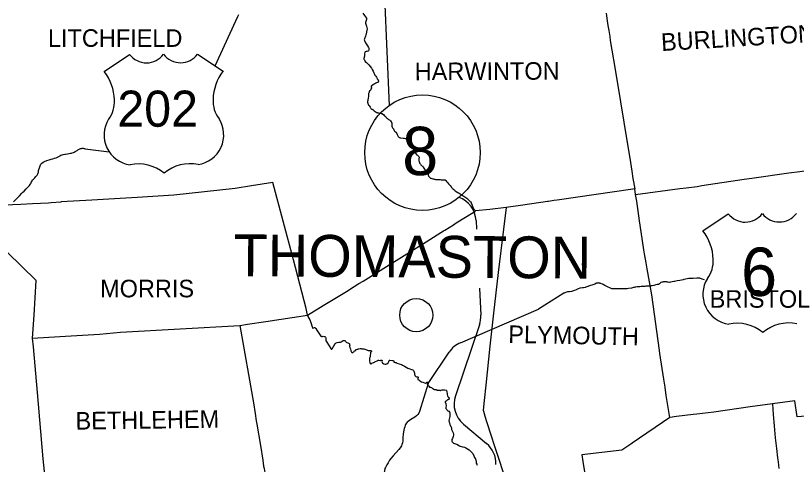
# Model space of a CAD drawing. Extents: x 0 to 2603, y -226 to 830.
# Drawn here: x 100.6 to 160.6, y 606.3 to 640.7 of the extents above; entities that cross this region are included whole.
import ezdxf

# ---------------------------------------------------------------- set-up
doc = ezdxf.new("R2010")
doc.units = 0
for name, color, linetype in [('CT_TSH_Map_Cities_Text', 7, 'Continuous'), ('CT_TSH_Map_Districts', 7, 'Continuous'), ('CT_TSH_Map_Town_Limits', 7, 'Continuous'), ('CT_TSH_Map_Town_Text', 7, 'Continuous'), ('CT_TSH_Map_US_and_State_Routes', 7, 'Continuous')]:
    doc.layers.add(name, color=color, linetype=linetype)

msp = doc.modelspace()

# ---------------------------------------------------------------- linework, layer by layer
at = {"layer": 'CT_TSH_Map_Cities_Text'}
msp.add_circle((131.429, 617.742), 1.277, dxfattribs=at)
at = {"layer": 'CT_TSH_Map_Districts'}
for points in [[(148.278, 627.02), (151.681, 627.475), (152.152, 627.53), (153.003, 627.633), (153.352, 627.689), (156.611, 628.19), (157.203, 628.271), (160.048, 628.681), (160.888, 628.784), (161.63, 628.881), (162.448, 629.002), (165.876, 629.461)], [(150.903, 609.889), (150.633, 611.58), (150.537, 612.202), (150.436, 612.824), (150.125, 614.791), (150.099, 615.029), (149.51, 619.3), (149.173, 621.288), (149.092, 621.768), (148.963, 622.452), (148.9, 622.761), (148.702, 624.138), (148.571, 624.979), (148.361, 626.488), (148.278, 627.02)], [(150.903, 609.889), (148.007, 607.903), (147.918, 607.835), (147.204, 607.367), (144.141, 607.01), (144.225, 606.511), (144.636, 603.968)]]:
    msp.add_lwpolyline(points, dxfattribs=at)
at = {"layer": 'CT_TSH_Map_Town_Limits'}
for points in [[(127.331, 640.938), (127.455, 640.745), (127.601, 640.541), (127.614, 640.495), (127.609, 640.455), (127.561, 640.307), (127.529, 640.227), (127.531, 640.169), (127.604, 639.928), (127.631, 639.828), (127.646, 639.732), (127.603, 639.511), (127.58, 639.323), (127.561, 639.269), (127.538, 639.175), (127.499, 639.089), (127.468, 639.033), (127.442, 638.962), (127.436, 638.89), (127.446, 638.841), (127.494, 638.708), (127.517, 638.657), (127.635, 638.498), (127.67, 638.437), (127.761, 638.299), (127.785, 638.237), (127.788, 638.162), (127.771, 638.092), (127.751, 638.043), (127.722, 638.017), (127.697, 638.01), (127.639, 637.997), (127.569, 637.997), (127.503, 637.973), (127.476, 637.923), (127.446, 637.811), (127.439, 637.636), (127.409, 637.459), (127.41, 637.413), (127.439, 637.345), (127.51, 637.225), (127.607, 637.138), (127.702, 637.035), (127.784, 636.956), (127.984, 636.707), (128.051, 636.61), (128.117, 636.489), (128.175, 636.361), (128.204, 636.305), (128.249, 636.187), (128.263, 636.143), (128.314, 636.091), (128.363, 636.028), (128.424, 635.907), (128.435, 635.89), (128.453, 635.861), (128.47, 635.834), (128.488, 635.812), (128.5, 635.798), (128.509, 635.766), (128.513, 635.746), (128.516, 635.723), (128.519, 635.694), (128.517, 635.676), (128.511, 635.657), (128.498, 635.64), (128.479, 635.622), (128.443, 635.603), (128.383, 635.58), (128.313, 635.551), (128.244, 635.517), (128.144, 635.449), (128.028, 635.381), (128.004, 635.362), (127.989, 635.353), (127.982, 635.347), (127.967, 635.335), (127.964, 635.325), (127.957, 635.308), (127.965, 635.261), (127.976, 635.224), (127.975, 635.186), (127.969, 635.154), (127.959, 635.115), (127.944, 635.088), (127.929, 635.059), (127.905, 635.027), (127.881, 635.004), (127.853, 634.976), (127.838, 634.959)], [(146.002, 640.945), (146.03, 640.736), (146.094, 640.347), (146.121, 640.161), (146.152, 639.995), (146.215, 639.601), (146.234, 639.451), (146.283, 639.145), (146.327, 638.839), (146.453, 638.085), (146.668, 636.769), (146.825, 635.823), (146.858, 635.695), (147.625, 631.006), (147.825, 629.8), (147.985, 628.81), (148.066, 628.248), (148.203, 627.455)], [(127.838, 634.959), (127.818, 634.904), (127.808, 634.854), (127.784, 634.801), (127.763, 634.766), (127.746, 634.73), (127.749, 634.697), (127.75, 634.612), (127.75, 634.573), (127.753, 634.54), (127.733, 634.438), (127.726, 634.368), (127.713, 634.311), (127.693, 634.22), (127.685, 634.158), (127.684, 634.138), (127.687, 634.104), (127.687, 634.076), (127.697, 634.043), (127.707, 633.997), (127.726, 633.938), (127.769, 633.875), (127.797, 633.847), (127.837, 633.795), (127.894, 633.718), (127.921, 633.674), (127.938, 633.635), (127.962, 633.6), (127.993, 633.575), (128.028, 633.557), (128.058, 633.541), (128.085, 633.526), (128.19, 633.441), (128.265, 633.376), (128.338, 633.326), (128.38, 633.315), (128.42, 633.299), (128.459, 633.293), (128.557, 633.273), (128.618, 633.255), (128.669, 633.249), (128.734, 633.242), (128.766, 633.231), (128.797, 633.218), (128.833, 633.195), (128.935, 633.115), (128.989, 633.063), (129.021, 633.023), (129.048, 632.996), (129.076, 632.962), (129.113, 632.928), (129.154, 632.876), (129.178, 632.852), (129.205, 632.837), (129.298, 632.78), (129.37, 632.735), (129.395, 632.715), (129.413, 632.692), (129.437, 632.664), (129.491, 632.6), (129.511, 632.577), (129.525, 632.547), (129.539, 632.521), (129.553, 632.49), (129.557, 632.469), (129.554, 632.438), (129.544, 632.339), (129.543, 632.285), (129.544, 632.25), (129.551, 632.218), (129.565, 632.198), (129.585, 632.175), (129.605, 632.138), (129.631, 632.115), (129.654, 632.079), (129.67, 632.058), (129.685, 632.036), (129.695, 631.99), (129.724, 631.922), (129.747, 631.879), (129.767, 631.852), (129.777, 631.839), (129.794, 631.831), (129.824, 631.827), (129.847, 631.824), (129.857, 631.788), (129.922, 631.682), (129.96, 631.61), (129.981, 631.569), (130.03, 631.469), (130.054, 631.431), (130.088, 631.407), (130.133, 631.375), (130.175, 631.357), (130.245, 631.357), (130.411, 631.346), (130.507, 631.332), (130.573, 631.321), (130.628, 631.306), (130.688, 631.261), (130.715, 631.22)], [(130.715, 631.22), (130.745, 631.189), (130.78, 631.156), (130.821, 631.125), (130.916, 631.026), (130.938, 630.991), (130.951, 630.969), (130.968, 630.93), (130.978, 630.904), (130.996, 630.823), (131.02, 630.745), (131.053, 630.678), (131.076, 630.652), (131.097, 630.618), (131.145, 630.564), (131.197, 630.49), (131.272, 630.362), (131.349, 630.228), (131.408, 630.103), (131.421, 630.083), (131.435, 630.072), (131.463, 630.059), (131.492, 630.051), (131.573, 629.987), (131.628, 629.926), (131.638, 629.863), (131.638, 629.819), (131.626, 629.779), (131.62, 629.722), (131.616, 629.685), (131.63, 629.594), (131.644, 629.532), (131.664, 629.475), (131.686, 629.43), (131.711, 629.39), (131.726, 629.353), (131.745, 629.329), (131.77, 629.288), (131.793, 629.256), (131.823, 629.233), (131.874, 629.208), (131.904, 629.202), (131.925, 629.171), (131.944, 629.144), (131.965, 629.101), (132.008, 629.025), (132.056, 628.963), (132.073, 628.938), (132.098, 628.897), (132.127, 628.88), (132.178, 628.842), (132.21, 628.813), (132.241, 628.793), (132.285, 628.77), (132.31, 628.75), (132.32, 628.729), (132.331, 628.699), (132.334, 628.641), (132.334, 628.582), (132.337, 628.534), (132.352, 628.494), (132.363, 628.454), (132.377, 628.413), (132.394, 628.386), (132.407, 628.367), (132.433, 628.339), (132.468, 628.303), (132.488, 628.286), (132.516, 628.27), (132.546, 628.256), (132.627, 628.228), (132.697, 628.213), (132.758, 628.2), (132.811, 628.194), (132.861, 628.185), (132.912, 628.169), (133.039, 628.152), (133.138, 628.151), (133.203, 628.153), (133.261, 628.159), (133.331, 628.14), (133.394, 628.142), (133.429, 628.142), (133.48, 628.144), (133.537, 628.145), (133.566, 628.146), (133.601, 628.14), (133.645, 628.131), (133.666, 628.115), (133.705, 628.073), (133.753, 628.005), (133.786, 627.97), (133.812, 627.944), (133.834, 627.924), (133.901, 627.838), (133.975, 627.748), (134.025, 627.697), (134.097, 627.604), (134.138, 627.55), (134.169, 627.516), (134.205, 627.489)], [(148.278, 627.02), (151.681, 627.475), (152.152, 627.53), (153.003, 627.633), (153.352, 627.689), (156.611, 628.19), (157.203, 628.271), (160.048, 628.681), (160.888, 628.784), (161.63, 628.881), (162.448, 629.002), (165.876, 629.461)], [(123.082, 617.737), (122.957, 618.259), (121.992, 621.988), (120.401, 627.917), (118.766, 627.682), (117.516, 627.46), (112.802, 626.95), (109.976, 626.777), (106.508, 626.575), (104.157, 626.438), (104.117, 626.429), (103.372, 626.362), (103.176, 626.354), (101.954, 626.288), (101.061, 626.24), (100.398, 626.21), (99.854, 626.177), (99.416, 626.152), (99.483, 623.59), (99.489, 623.377), (99.497, 623.12), (99.5, 623.08)], [(134.205, 627.489), (134.235, 627.454), (134.312, 627.384), (134.409, 627.302), (134.481, 627.249), (134.618, 627.164), (134.717, 627.109), (134.794, 627.067), (134.871, 627.015), (134.952, 626.958), (135.021, 626.911), (135.087, 626.869), (135.163, 626.83), (135.23, 626.778), (135.298, 626.72), (135.386, 626.647), (135.475, 626.57), (135.522, 626.52), (135.565, 626.481), (135.606, 626.438), (135.638, 626.379), (135.69, 626.248), (135.717, 626.173), (135.76, 626.051), (135.797, 625.964), (135.836, 625.917), (135.878, 625.856), (135.929, 625.804), (135.978, 625.754), (135.982, 625.748)], [(148.203, 627.455), (148.064, 627.424), (142.244, 626.581), (142.004, 626.545), (141.582, 626.48), (141.495, 626.459), (139.609, 626.176), (138.331, 626.019)], [(148.278, 627.02), (148.203, 627.455)], [(150.903, 609.889), (150.633, 611.58), (150.537, 612.202), (150.436, 612.824), (150.125, 614.791), (150.099, 615.029), (149.51, 619.3), (149.173, 621.288), (149.092, 621.768), (148.963, 622.452), (148.9, 622.761), (148.702, 624.138), (148.571, 624.979), (148.361, 626.488), (148.278, 627.02)], [(123.082, 617.737), (124.282, 618.477), (126.059, 619.557), (126.657, 619.929), (127.024, 620.162), (127.335, 620.358), (129.337, 621.603), (132.196, 623.384), (133.32, 624.084), (133.524, 624.216), (133.615, 624.27), (134.277, 624.689), (134.494, 624.823), (135.788, 625.637), (135.919, 625.714), (135.973, 625.747), (135.982, 625.748)], [(138.331, 626.019), (137.078, 625.861), (135.982, 625.748)], [(138.331, 626.019), (137.723, 621.006), (137.355, 617.881), (137.077, 615.36), (136.757, 612.369), (136.636, 611.187), (136.553, 610.437), (136.656, 610.108), (136.665, 610.067), (137.111, 608.697), (137.489, 607.518), (137.807, 606.532), (138.825, 603.397), (138.97, 602.938)], [(101.957, 615.974), (102.069, 617.732), (102.222, 620.412), (100.003, 622.578), (99.738, 622.841), (99.5, 623.08)], [(117.885, 616.956), (118.455, 617.038), (119.873, 617.242), (123.082, 617.737)], [(123.082, 617.737), (123.09, 617.677), (123.091, 617.634), (123.169, 617.506), (123.263, 617.374), (123.334, 617.184), (123.426, 616.851), (123.446, 616.799), (123.453, 616.771), (123.476, 616.739), (123.487, 616.733), (123.549, 616.755), (123.613, 616.8), (123.623, 616.801), (123.665, 616.765), (123.701, 616.717), (123.778, 616.588), (123.936, 616.35), (124.097, 616.138), (124.128, 616.116), (124.152, 616.112), (124.222, 616.108), (124.281, 616.115), (124.344, 616.11), (124.392, 616.1), (124.408, 616.094), (124.458, 616.046), (124.48, 616.009), (124.49, 615.969), (124.49, 615.924), (124.483, 615.899), (124.489, 615.763), (124.496, 615.745), (124.725, 615.375), (124.86, 615.171), (124.895, 615.13), (124.929, 615.12), (124.946, 615.122), (124.969, 615.145), (125.07, 615.324), (125.159, 615.513), (125.174, 615.536), (125.212, 615.571), (125.276, 615.607), (125.354, 615.636), (125.48, 615.667), (125.503, 615.669), (125.546, 615.674), (125.614, 615.672), (125.667, 615.692), (125.803, 615.791), (125.823, 615.8), (125.89, 615.803), (125.94, 615.787), (125.988, 615.742), (125.996, 615.733), (126.013, 615.705), (126.042, 615.665), (126.091, 615.637), (126.171, 615.616), (126.222, 615.595), (126.261, 615.574), (126.29, 615.548), (126.304, 615.494), (126.312, 615.422), (126.31, 615.368), (126.329, 615.241), (126.343, 615.202), (126.371, 615.153), (126.383, 615.117), (126.39, 615.025), (126.395, 614.998), (126.455, 614.905), (126.488, 614.876), (126.527, 614.852), (126.591, 614.885), (126.623, 614.927), (126.667, 614.969), (126.722, 615.011), (126.81, 615.089), (126.85, 615.112), (126.908, 615.137), (126.934, 615.135), (126.978, 615.147), (127.023, 615.153), (127.109, 615.181), (127.187, 615.173), (127.235, 615.151), (127.337, 615.158), (127.386, 615.149), (127.471, 615.126), (127.555, 615.107), (127.616, 615.077), (127.648, 615.057), (127.723, 615.026), (127.825, 615.018), (127.917, 615.025), (127.983, 615.005), (127.998, 614.991), (128.006, 614.973), (127.999, 614.937)], [(101.957, 615.974), (104.057, 616.095), (107.091, 616.284), (108.702, 616.421), (117.885, 616.956)], [(117.885, 616.956), (118.922, 611.006), (119.043, 610.194), (119.14, 609.616), (119.181, 609.369), (119.469, 607.731), (119.629, 606.607), (119.698, 606.145), (119.733, 605.949), (119.834, 605.352), (119.932, 604.822), (120.01, 604.351), (120.08, 603.954), (120.131, 603.699)], [(103.28, 601.876), (102.777, 606.697), (102.335, 611.806), (102.011, 615.302), (101.957, 615.974)], [(127.999, 614.937), (127.986, 614.918), (127.968, 614.91), (127.943, 614.892), (127.923, 614.883), (127.906, 614.852), (127.9, 614.791), (127.872, 614.64), (127.885, 614.532), (127.843, 614.448), (127.826, 614.365), (127.827, 614.275), (127.822, 614.221), (127.856, 614.08), (127.88, 614.037), (127.903, 614.015), (127.924, 614.002), (127.972, 614.011), (128.014, 614.054), (128.128, 614.103), (128.179, 614.115), (128.208, 614.129), (128.24, 614.153), (128.472, 614.257), (128.503, 614.282), (128.535, 614.287), (128.561, 614.285), (128.648, 614.259), (128.683, 614.264), (128.716, 614.284), (128.737, 614.289), (128.771, 614.285), (128.785, 614.279), (128.797, 614.259), (128.802, 614.226), (128.792, 614.18), (128.795, 614.12), (128.801, 614.096), (128.819, 614.069), (128.851, 614.047), (128.927, 614.007), (129.032, 613.97), (129.053, 613.969), (129.083, 613.975), (129.16, 614.002), (129.283, 614.098), (129.303, 614.131), (129.327, 614.178), (129.341, 614.268), (129.362, 614.282), (129.376, 614.284), (129.407, 614.271), (129.591, 614.263), (129.653, 614.267), (129.675, 614.259), (129.687, 614.245), (129.695, 614.176), (129.692, 614.155), (129.697, 614.135), (129.719, 614.123), (129.753, 614.118), (129.816, 614.113), (129.87, 614.099), (129.942, 614.057), (130.284, 613.944), (130.38, 613.896), (130.51, 613.821), (130.775, 613.678), (130.933, 613.61), (131.054, 613.57), (131.089, 613.555), (131.159, 613.536), (131.199, 613.518), (131.218, 613.501), (131.248, 613.436), (131.279, 613.293), (131.288, 613.238), (131.328, 613.117), (131.344, 613.077), (131.37, 613.044), (131.398, 613.019), (131.433, 613.002), (131.506, 612.999), (131.555, 613.002), (131.58, 612.975), (131.584, 612.946), (131.564, 612.924), (131.557, 612.874), (131.544, 612.852), (131.54, 612.81), (131.543, 612.8), (131.601, 612.781), (131.63, 612.765), (131.651, 612.74), (131.703, 612.702), (131.818, 612.63), (131.921, 612.581), (132.067, 612.542), (132.141, 612.519), (132.161, 612.518), (132.18, 612.524)], [(132.18, 612.524), (132.197, 612.536), (132.222, 612.562), (132.241, 612.592), (132.288, 612.604), (132.303, 612.597), (132.308, 612.575), (132.3, 612.548), (132.298, 612.519), (132.273, 612.453), (132.27, 612.429), (132.286, 612.394), (132.318, 612.367), (132.361, 612.31), (132.413, 612.278), (132.427, 612.245), (132.455, 612.212), (132.469, 612.204), (132.531, 612.197), (132.586, 612.183), (132.647, 612.144), (132.708, 612.114), (132.767, 612.056), (132.813, 612.026), (132.849, 612.02), (132.927, 612.029), (132.963, 612.028), (132.977, 612.022), (132.994, 611.985), (133.024, 611.974), (133.099, 611.98), (133.127, 611.971), (133.226, 611.966), (133.291, 611.958), (133.322, 611.96), (133.345, 611.969), (133.349, 611.966), (133.42, 611.998), (133.446, 611.998), (133.492, 612.006), (133.588, 611.999), (133.712, 611.974), (133.739, 611.942), (133.771, 611.832), (133.792, 611.727), (133.798, 611.633), (133.83, 611.554), (133.84, 611.505), (133.883, 611.437), (133.91, 611.421), (133.937, 611.412), (133.958, 611.399), (133.97, 611.369), (133.956, 611.33), (133.901, 611.27), (133.838, 611.246), (133.819, 611.232), (133.749, 611.151), (133.727, 611.133), (133.715, 611.147), (133.651, 611.074), (133.654, 611.029), (133.692, 610.97), (133.706, 610.935), (133.732, 610.765), (133.707, 610.67), (133.701, 610.616), (133.704, 610.575), (133.722, 610.539), (133.775, 610.492), (133.804, 610.453), (133.885, 610.381), (133.921, 610.361), (133.983, 610.298), (134.001, 610.256), (134.009, 610.216), (133.997, 610.03), (133.996, 609.966), (133.984, 609.863), (133.949, 609.746), (133.937, 609.66), (133.952, 609.523), (133.966, 609.464), (134.014, 609.345), (134.037, 609.299), (134.066, 609.22), (134.095, 609.165), (134.125, 609.04), (134.145, 608.969), (134.262, 608.708), (134.281, 608.609), (134.289, 608.515), (134.268, 608.426), (134.208, 608.26), (134.167, 608.178), (134.165, 608.053), (134.182, 608.013), (134.201, 607.987), (134.283, 607.916), (134.36, 607.87), (134.44, 607.849)], [(168.492, 612.2), (165.733, 611.819), (165.253, 611.754), (162.823, 611.449), (162.001, 611.328), (161.34, 611.229), (161.344, 611.128), (161.355, 611.069), (161.398, 611.009), (161.535, 610.889), (161.577, 610.843), (161.607, 610.8), (161.636, 610.727), (161.689, 610.543), (161.701, 610.445), (161.705, 610.354), (161.692, 610.128), (161.704, 610.002), (160.673, 609.923), (160.516, 611.15), (158.799, 610.931)], [(158.799, 610.931), (157.064, 610.704), (154.277, 610.284), (152.979, 610.134), (152.687, 610.106), (151.411, 609.952), (150.903, 609.889)], [(158.799, 610.931), (158.844, 610.096), (158.914, 609.238), (159.001, 608.305), (159.094, 607.508), (159.184, 606.768), (159.224, 606.47), (159.277, 605.972)], [(150.903, 609.889), (148.007, 607.903), (147.918, 607.835), (147.204, 607.367), (144.141, 607.01), (144.225, 606.511), (144.636, 603.968)], [(134.44, 607.849), (134.537, 607.838), (134.743, 607.709), (134.801, 607.688), (134.976, 607.637), (135.039, 607.626), (135.119, 607.595), (135.235, 607.539), (135.477, 607.403), (135.551, 607.344), (135.615, 607.277), (135.661, 607.217), (135.758, 607.129), (135.775, 607.103), (135.845, 606.923), (135.876, 606.866), (135.898, 606.812), (135.951, 606.724), (135.976, 606.691), (135.996, 606.581), (136.01, 606.557), (136.015, 606.539), (136.022, 606.451), (136.032, 606.377), (136.067, 606.298), (136.11, 606.227)]]:
    msp.add_lwpolyline(points, dxfattribs=at)
at = {"layer": 'CT_TSH_Map_US_and_State_Routes'}
for p, q in [((128.854, 644.938), (129.353, 633.855)), ((117.567, 640.349), (117.717, 640.676)), ((117.717, 640.676), (117.788, 640.822)), ((115.985, 636.898), (117.567, 640.349)), ((107.444, 636.451), (109.398, 637.767)), ((114.63, 637.799), (116.594, 636.493)), ((107.445, 636.453), (107.444, 636.451)), ((105.705, 630.55), (105.765, 630.556)), ((104.773, 630.154), (104.875, 630.176)), ((100.952, 626.916), (101.134, 627.101)), ((136.018, 625.009), (136.051, 624.346)), ((153.441, 624.215), (155.394, 625.531)), ((153.442, 624.217), (153.441, 624.215)), ((136.274, 619.803), (136.376, 617.743)), ((134.816, 615.62), (140.816, 618.21)), ((136.274, 617.007), (134.436, 611.548)), ((132.331, 612.48), (133.946, 614.895)), ((135.044, 609.378), (136.828, 607.88))]:
    msp.add_line(p, q, dxfattribs=at)
for points in [[(105.086, 630.235), (105.158, 630.265), (105.223, 630.3), (105.373, 630.397)], [(105.373, 630.397), (105.437, 630.439), (105.522, 630.492), (105.577, 630.515), (105.632, 630.534), (105.658, 630.542), (105.705, 630.55)], [(105.765, 630.556), (105.831, 630.556), (105.897, 630.549), (105.945, 630.541)], [(105.945, 630.541), (105.998, 630.527), (107.831, 630.291)], [(103.219, 629.673), (103.384, 629.719), (103.506, 629.75), (103.644, 629.788), (103.756, 629.825), (103.915, 629.894)], [(103.915, 629.894), (103.975, 629.926), (104.028, 629.951), (104.057, 629.977)], [(104.057, 629.977), (104.123, 630.021), (104.215, 630.066), (104.31, 630.091), (104.424, 630.102), (104.494, 630.106), (104.647, 630.131)], [(104.647, 630.131), (104.731, 630.145), (104.773, 630.154)], [(104.875, 630.176), (104.935, 630.19), (104.994, 630.206), (105.086, 630.235)], [(102.409, 628.8), (102.411, 628.858), (102.434, 628.936), (102.472, 629.058), (102.536, 629.214), (102.594, 629.328), (102.67, 629.424), (102.758, 629.494), (102.871, 629.552), (103.046, 629.618), (103.219, 629.673)], [(102.211, 628.378), (102.26, 628.439), (102.301, 628.489), (102.335, 628.545), (102.362, 628.594), (102.39, 628.679)], [(102.39, 628.679), (102.403, 628.728), (102.408, 628.774), (102.409, 628.8)], [(101.79, 627.82), (101.84, 627.913), (101.868, 627.98), (101.91, 628.059), (101.956, 628.122), (102.022, 628.192), (102.124, 628.285), (102.211, 628.378)], [(101.298, 627.273), (101.454, 627.433), (101.667, 627.652)], [(101.667, 627.652), (101.712, 627.705), (101.757, 627.766), (101.79, 627.82)], [(100.483, 626.433), (100.7, 626.655), (100.768, 626.727), (100.952, 626.916)], [(101.134, 627.101), (101.204, 627.176), (101.298, 627.273)], [(145.36, 620.209), (145.331, 620.204), (145.283, 620.188), (145.138, 620.133)], [(145.557, 620.183), (145.519, 620.194), (145.447, 620.209), (145.404, 620.213), (145.36, 620.209)], [(145.73, 620.114), (145.616, 620.171), (145.557, 620.183)], [(150.217, 620.256), (150.181, 620.224), (150.166, 620.209), (150.126, 620.156), (150.116, 620.143), (150.109, 620.138), (150.021, 620.102), (149.928, 620.082)], [(150.486, 620.291), (150.422, 620.288), (150.359, 620.28), (150.288, 620.27), (150.217, 620.256)], [(150.886, 620.25), (150.78, 620.272), (150.71, 620.282), (150.647, 620.288), (150.599, 620.29), (150.546, 620.291), (150.486, 620.291)], [(151.251, 620.325), (151.202, 620.315), (150.948, 620.262), (150.886, 620.25)], [(151.467, 620.369), (151.251, 620.325)], [(151.681, 620.413), (151.467, 620.369)], [(151.924, 620.463), (151.681, 620.413)], [(151.978, 620.475), (151.924, 620.463)], [(152.242, 620.528), (151.978, 620.475)], [(152.354, 620.551), (152.242, 620.528)], [(152.471, 620.556), (152.354, 620.551)], [(152.694, 620.565), (152.471, 620.556)], [(152.967, 620.573), (152.694, 620.565)], [(153.219, 620.581), (152.967, 620.573)], [(153.399, 620.509), (153.219, 620.581)], [(153.562, 620.442), (153.399, 620.509)], [(143.34, 619.562), (143.189, 619.533), (143.089, 619.527), (143.031, 619.52), (142.968, 619.502), (142.846, 619.461), (142.792, 619.439)], [(144.048, 619.816), (143.978, 619.804), (143.85, 619.771), (143.698, 619.695), (143.569, 619.639), (143.432, 619.584), (143.34, 619.562)], [(144.532, 619.911), (144.457, 619.881), (144.4, 619.869), (144.278, 619.843), (144.191, 619.832), (144.048, 619.816)], [(144.98, 620.076), (144.722, 619.986), (144.532, 619.911)], [(145.138, 620.133), (144.98, 620.076)], [(145.779, 620.09), (145.73, 620.114)], [(145.961, 620.001), (145.917, 620.023), (145.779, 620.09)], [(146.175, 619.886), (145.961, 620.001)], [(146.286, 619.826), (146.175, 619.886)], [(146.454, 619.766), (146.286, 619.826)], [(146.461, 619.764), (146.454, 619.766)], [(146.542, 619.759), (146.483, 619.76), (146.461, 619.764)], [(146.674, 619.758), (146.542, 619.759)], [(147.025, 619.76), (146.797, 619.757), (146.674, 619.758)], [(147.455, 619.771), (147.296, 619.768), (147.025, 619.76)], [(147.528, 619.772), (147.455, 619.771)], [(147.72, 619.779), (147.616, 619.774), (147.528, 619.772)], [(147.956, 619.825), (147.72, 619.779)], [(148.037, 619.844), (147.956, 619.825)], [(148.167, 619.874), (148.12, 619.864), (148.037, 619.844)], [(148.204, 619.882), (148.167, 619.874)], [(148.285, 619.9), (148.204, 619.882)], [(148.442, 619.923), (148.404, 619.921), (148.285, 619.9)], [(148.48, 619.924), (148.442, 619.923)], [(148.504, 619.925), (148.48, 619.924)], [(148.602, 619.928), (148.504, 619.925)], [(148.795, 619.937), (148.697, 619.931), (148.602, 619.928)], [(148.839, 619.94), (148.795, 619.937)], [(148.977, 619.95), (148.839, 619.94)], [(149.219, 619.97), (149.168, 619.97), (149.069, 619.96), (148.977, 619.95)], [(149.269, 619.971), (149.219, 619.97)], [(149.928, 620.082), (149.832, 620.063), (149.685, 620.03), (149.559, 620), (149.546, 619.998), (149.471, 619.987), (149.413, 619.979), (149.341, 619.968), (149.307, 619.97), (149.269, 619.971)], [(142.759, 619.422), (140.816, 618.21)], [(142.792, 619.439), (142.759, 619.422)], [(132.332, 612.485), (131.683, 610.337), (131.622, 610.219), (131.534, 610.109), (131.437, 610.01), (131.313, 609.915), (131.011, 609.724)], [(130.901, 609.659), (130.791, 609.578), (130.725, 609.51), (130.662, 609.428), (130.608, 609.348), (130.566, 609.265), (130.536, 609.165), (130.505, 609.043), (130.47, 608.908)], [(131.011, 609.724), (130.901, 609.659)], [(130.47, 608.908), (130.436, 608.774), (130.413, 608.6), (130.405, 608.352), (130.384, 608.081), (130.358, 607.936), (130.317, 607.808)], [(130.317, 607.808), (130.281, 607.708), (130.23, 607.613), (130.184, 607.538), (130.077, 607.425), (129.661, 606.943), (129.462, 606.724)], [(129.462, 606.724), (129.38, 606.591), (129.273, 606.403), (129.216, 606.328), (129.159, 606.241), (129.118, 606.149), (129.099, 606.101), (129.056, 606.034), (129.023, 605.966), (128.989, 605.78), (128.905, 605.38), (128.898, 605.289), (128.87, 605.188), (128.833, 605.049), (128.767, 604.786), (128.7, 604.529)]]:
    msp.add_lwpolyline(points, dxfattribs=at)
msp.add_circle((131.903, 630.222), 4.438, dxfattribs=at)
for centre, radius, start, end in [((110.699, 638.753), 1.632, 217.13773, 323.39794), ((113.316, 638.766), 1.632, 217.13773, 323.39794), ((104.518, 634.155), 3.722, 1.8086, 38.14282), ((119.539, 634.225), 3.722, 142.39285, 178.72707), ((106.011, 634.131), 2.232, 323.17424, 3.61929), ((118.047, 634.187), 2.232, 176.91638, 217.36143), ((109.753, 631.568), 2.308, 147.93815, 262.13773), ((114.329, 631.589), 2.308, 278.39793, 32.59751), ((110.104, 626.347), 3.009, 49.66654, 102.79664), ((114.027, 626.366), 3.009, 77.73902, 130.86913), ((134.02, 624.911), 2, 2.8215, 69.72705), ((156.695, 626.517), 1.632, 217.13773, 323.39794), ((159.313, 626.529), 1.632, 217.13773, 323.39794), ((150.515, 621.918), 3.722, 1.8086, 38.14282), ((152.007, 621.894), 2.232, 323.17424, 3.61929), ((155.749, 619.331), 2.308, 147.93815, 262.13773), ((134.378, 617.645), 2, 341.39091, 2.8215), ((156.1, 614.111), 3.009, 49.66654, 102.79664), ((160.023, 614.129), 3.009, 77.73902, 130.86913), ((135.608, 613.783), 2, 113.3486, 146.22792), ((136.331, 610.91), 2, 161.39091, 229.95851), ((135.541, 606.349), 2, 357.94504, 49.95851)]:
    msp.add_arc(centre, radius, start, end, dxfattribs=at)

# ---------------------------------------------------------------- texts
at = {"layer": 'CT_TSH_Map_Cities_Text'}
msp.add_text('THOMASTON', height=3.2147, rotation=359.58465, dxfattribs=at).set_placement((117.384, 620.738))
at = {"layer": 'CT_TSH_Map_Town_Text'}
for s, rotation, p in [('BURLINGTON', 3.40779, (150.269, 638.025)), ('HARWINTON', 0.23979, (131.308, 635.785)), ('PLYMOUTH', 358.95275, (138.484, 615.606)), ('BETHLEHEM', 0.78934, (105.258, 608.942))]:
    msp.add_text(s, height=1.35, rotation=rotation, dxfattribs=at).set_placement(p)
for s, p in [('LITCHFIELD', (103.131, 638.35)), ('MORRIS', (107.139, 619.11)), ('BRISTOL', (153.965, 618.309))]:
    msp.add_text(s, height=1.35, dxfattribs=at).set_placement(p)
at = {"layer": 'CT_TSH_Map_US_and_State_Routes'}
for s, height, p in [('202', 2.7737, (108.467, 632.213)), ('8', 3.714, (130.345, 628.495)), ('6', 3.714, (156.377, 619.214))]:
    msp.add_text(s, height=height, dxfattribs=at).set_placement(p)

doc.saveas('drawing.dxf')
